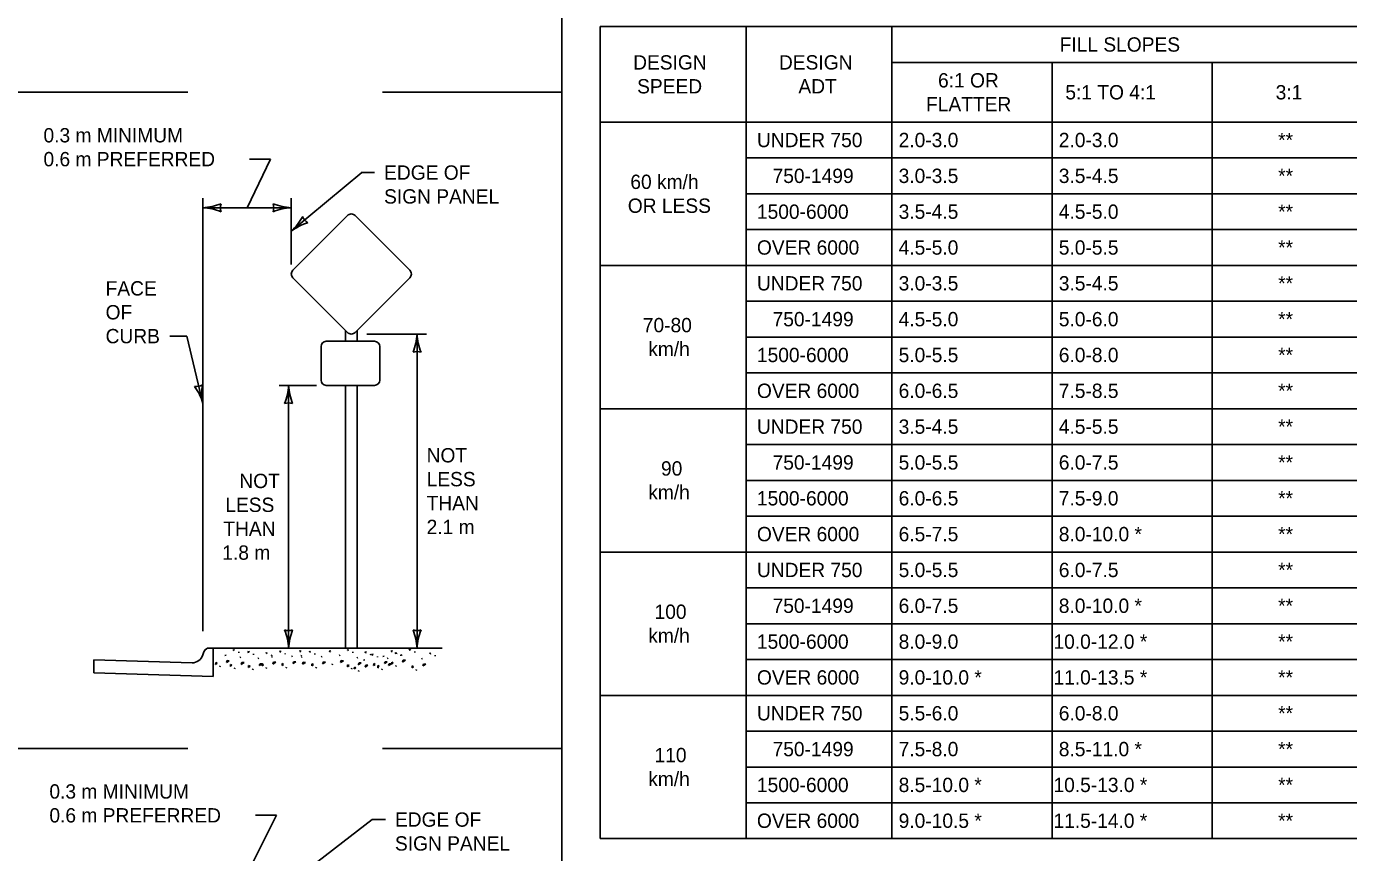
# Model space of a CAD drawing. Extents: x 49991.4 to 50021, y 49987.6 to 50011.4.
# Drawn here: x 50005.83 to 50011.36, y 49990.11 to 49993.57 of the extents above; entities that cross this region are included whole.
import ezdxf

# ---------------------------------------------------------------- set-up
doc = ezdxf.new("R2010")
doc.units = 0
for name, color, linetype in [('Level 1', 7, 'Continuous'), ('Level 2', 7, 'Continuous'), ('Level 3', 7, 'Continuous')]:
    doc.layers.add(name, color=color, linetype=linetype)

msp = doc.modelspace()

# ---------------------------------------------------------------- linework, layer by layer
at = {"layer": 'Level 1'}
for p, q in [((50006.9416, 49992.5484), (50007.1702, 49992.7772)), ((50007.202, 49992.7772), (50007.4309, 49992.5484)), ((50007.1702, 49992.2877), (50006.9416, 49992.5166)), ((50007.4309, 49992.5166), (50007.202, 49992.2877)), ((50007.1618, 49992.2506), (50007.1618, 49992.2961)), ((50007.2104, 49992.2506), (50007.2104, 49992.2961)), ((50007.0595, 49992.0878), (50007.0595, 49992.2291)), ((50007.081, 49992.2506), (50007.2836, 49992.2506)), ((50007.3051, 49992.2291), (50007.3051, 49992.0878)), ((50007.2836, 49992.0663), (50007.081, 49992.0663)), ((50007.1618, 49990.9661), (50007.1618, 49992.0663)), ((50007.2104, 49990.9661), (50007.2104, 49992.0663)), ((50006.6082, 49990.9661), (50006.5913, 49990.9661)), ((50006.6082, 49990.9661), (50007.5665, 49990.9661)), ((50006.6082, 49990.8476), (50006.6082, 49990.9661)), ((50006.6622, 49990.9368), (50006.6576, 49990.9352)), ((50006.6922, 49990.9563), (50006.6942, 49990.961)), ((50006.6966, 49990.9574), (50006.6922, 49990.9563)), ((50006.6942, 49990.961), (50006.6966, 49990.9574)), ((50006.7151, 49990.9467), (50006.7156, 49990.9503)), ((50006.7238, 49990.9288), (50006.7192, 49990.9272)), ((50006.7538, 49990.9483), (50006.7558, 49990.953)), ((50006.7583, 49990.9494), (50006.7538, 49990.9483)), ((50006.7558, 49990.953), (50006.7583, 49990.9494)), ((50006.7767, 49990.9387), (50006.7772, 49990.9423)), ((50006.7997, 49990.924), (50006.7951, 49990.9225)), ((50006.8297, 49990.9436), (50006.8318, 49990.9483)), ((50006.8342, 49990.9446), (50006.8297, 49990.9436)), ((50006.8318, 49990.9483), (50006.8342, 49990.9446)), ((50006.8566, 49990.9305), (50006.852, 49990.9289)), ((50006.8526, 49990.934), (50006.8531, 49990.9376)), ((50006.8866, 49990.95), (50006.8886, 49990.9547)), ((50006.8911, 49990.9511), (50006.8866, 49990.95)), ((50006.8886, 49990.9547), (50006.8911, 49990.9511)), ((50006.9095, 49990.9404), (50006.91, 49990.944)), ((50006.9404, 49990.932), (50006.9358, 49990.9305)), ((50006.9704, 49990.9516), (50006.9724, 49990.9563)), ((50006.9749, 49990.9527), (50006.9704, 49990.9516)), ((50006.9724, 49990.9563), (50006.9749, 49990.9527)), ((50006.9808, 49990.9298), (50006.9762, 49990.9282)), ((50006.9768, 49990.9333), (50006.9773, 49990.9369)), ((50007.0108, 49990.9493), (50007.0128, 49990.954)), ((50007.0153, 49990.9504), (50007.0108, 49990.9493)), ((50007.0128, 49990.954), (50007.0153, 49990.9504)), ((50007.0337, 49990.9397), (50007.0342, 49990.9433)), ((50007.0646, 49990.9313), (50007.06, 49990.9298)), ((50007.0946, 49990.9509), (50007.0966, 49990.9556)), ((50007.0991, 49990.952), (50007.0946, 49990.9509)), ((50007.0966, 49990.9556), (50007.0991, 49990.952)), ((50007.1396, 49990.9368), (50007.135, 49990.9352)), ((50007.1695, 49990.9563), (50007.1716, 49990.961)), ((50007.174, 49990.9574), (50007.1695, 49990.9563)), ((50007.1716, 49990.961), (50007.174, 49990.9574)), ((50007.1924, 49990.9467), (50007.1929, 49990.9503)), ((50007.2139, 49990.9272), (50007.2093, 49990.9256)), ((50007.2439, 49990.9467), (50007.2459, 49990.9514)), ((50007.2483, 49990.9478), (50007.2439, 49990.9467)), ((50007.2459, 49990.9514), (50007.2483, 49990.9478)), ((50007.2668, 49990.9371), (50007.2673, 49990.9408)), ((50007.2722, 49990.9372), (50007.2743, 49990.942)), ((50007.2767, 49990.9383), (50007.2722, 49990.9372)), ((50007.2743, 49990.942), (50007.2767, 49990.9383)), ((50007.2952, 49990.9277), (50007.2956, 49990.9313)), ((50007.3229, 49990.932), (50007.3183, 49990.9305)), ((50007.3403, 49990.924), (50007.3357, 49990.9225)), ((50007.3529, 49990.9516), (50007.355, 49990.9563)), ((50007.3574, 49990.9527), (50007.3529, 49990.9516)), ((50007.355, 49990.9563), (50007.3574, 49990.9527)), ((50007.3702, 49990.9436), (50007.3723, 49990.9483)), ((50007.3747, 49990.9446), (50007.3702, 49990.9436)), ((50007.3723, 49990.9483), (50007.3747, 49990.9446)), ((50007.3758, 49990.942), (50007.3763, 49990.9456)), ((50007.3932, 49990.934), (50007.3936, 49990.9376)), ((50007.3987, 49990.9383), (50007.3941, 49990.9368)), ((50007.4287, 49990.9579), (50007.4308, 49990.9626)), ((50007.4332, 49990.959), (50007.4287, 49990.9579)), ((50007.4308, 49990.9626), (50007.4332, 49990.959)), ((50007.4516, 49990.9483), (50007.4521, 49990.9519)), ((50007.5141, 49990.942), (50007.5161, 49990.9467)), ((50007.5186, 49990.9431), (50007.5141, 49990.942)), ((50007.5161, 49990.9467), (50007.5186, 49990.9431)), ((50007.537, 49990.9324), (50007.5375, 49990.936)), ((50006.5199, 49990.9044), (50006.1083, 49990.9168)), ((50006.1083, 49990.9168), (50006.1083, 49990.8627)), ((50006.6185, 49990.8978), (50006.619, 49990.9061)), ((50006.6248, 49990.9028), (50006.6185, 49990.8978)), ((50006.619, 49990.9061), (50006.6248, 49990.9028)), ((50006.6373, 49990.8916), (50006.6358, 49990.8874)), ((50006.6668, 49990.9137), (50006.6635, 49990.9058)), ((50006.6635, 49990.9058), (50006.6757, 49990.9135)), ((50006.6757, 49990.9135), (50006.6668, 49990.9137)), ((50006.6802, 49990.8898), (50006.6806, 49990.8981)), ((50006.6865, 49990.8948), (50006.6802, 49990.8898)), ((50006.6806, 49990.8981), (50006.6865, 49990.8948)), ((50006.6989, 49990.8836), (50006.6974, 49990.8794)), ((50006.7284, 49990.9057), (50006.7251, 49990.8978)), ((50006.7251, 49990.8978), (50006.7373, 49990.9055)), ((50006.7373, 49990.9055), (50006.7284, 49990.9057)), ((50006.7561, 49990.8851), (50006.7566, 49990.8933)), ((50006.7624, 49990.8901), (50006.7561, 49990.8851)), ((50006.7566, 49990.8933), (50006.7624, 49990.8901)), ((50006.7749, 49990.8789), (50006.7733, 49990.8747)), ((50006.8043, 49990.901), (50006.8011, 49990.8931)), ((50006.8011, 49990.8931), (50006.8132, 49990.9007)), ((50006.8132, 49990.9007), (50006.8043, 49990.901)), ((50006.813, 49990.8915), (50006.8134, 49990.8998)), ((50006.8193, 49990.8965), (50006.813, 49990.8915)), ((50006.8134, 49990.8998), (50006.8193, 49990.8965)), ((50006.8318, 49990.8853), (50006.8302, 49990.8811)), ((50006.8612, 49990.9074), (50006.8579, 49990.8995)), ((50006.8579, 49990.8995), (50006.8701, 49990.9072)), ((50006.8701, 49990.9072), (50006.8612, 49990.9074)), ((50006.8968, 49990.8931), (50006.8972, 49990.9013)), ((50006.9031, 49990.8981), (50006.8968, 49990.8931)), ((50006.8972, 49990.9013), (50006.9031, 49990.8981)), ((50006.9156, 49990.8869), (50006.914, 49990.8827)), ((50006.945, 49990.909), (50006.9418, 49990.9011)), ((50006.9418, 49990.9011), (50006.9539, 49990.9087)), ((50006.9539, 49990.9087), (50006.945, 49990.909)), ((50006.9854, 49990.9067), (50006.9821, 49990.8988)), ((50006.9821, 49990.8988), (50006.9943, 49990.9065)), ((50006.9943, 49990.9065), (50006.9854, 49990.9067)), ((50007.021, 49990.8924), (50007.0214, 49990.9006)), ((50007.0273, 49990.8974), (50007.021, 49990.8924)), ((50007.0214, 49990.9006), (50007.0273, 49990.8974)), ((50007.0398, 49990.8862), (50007.0382, 49990.882)), ((50007.0692, 49990.9083), (50007.066, 49990.9004)), ((50007.066, 49990.9004), (50007.0781, 49990.908)), ((50007.0781, 49990.908), (50007.0692, 49990.9083)), ((50007.1076, 49990.9008), (50007.106, 49990.8966)), ((50007.1442, 49990.9137), (50007.1409, 49990.9058)), ((50007.1409, 49990.9058), (50007.153, 49990.9135)), ((50007.153, 49990.9135), (50007.1442, 49990.9137)), ((50007.1702, 49990.8883), (50007.1707, 49990.8965)), ((50007.1766, 49990.8932), (50007.1702, 49990.8883)), ((50007.1707, 49990.8965), (50007.1766, 49990.8932)), ((50007.189, 49990.8821), (50007.1875, 49990.8778)), ((50007.1986, 49990.8788), (50007.1991, 49990.887)), ((50007.2049, 49990.8838), (50007.1986, 49990.8788)), ((50007.1991, 49990.887), (50007.2049, 49990.8838)), ((50007.2185, 49990.9041), (50007.2152, 49990.8963)), ((50007.2152, 49990.8963), (50007.2274, 49990.9039)), ((50007.2174, 49990.8726), (50007.2158, 49990.8684)), ((50007.2274, 49990.9039), (50007.2185, 49990.9041)), ((50007.2423, 49990.9177), (50007.2377, 49990.9161)), ((50007.2469, 49990.8947), (50007.2436, 49990.8868)), ((50007.2436, 49990.8868), (50007.2557, 49990.8944)), ((50007.2557, 49990.8944), (50007.2469, 49990.8947)), ((50007.2793, 49990.8931), (50007.2798, 49990.9013)), ((50007.2856, 49990.8981), (50007.2793, 49990.8931)), ((50007.2798, 49990.9013), (50007.2856, 49990.8981)), ((50007.2981, 49990.8869), (50007.2965, 49990.8827)), ((50007.2966, 49990.8851), (50007.2971, 49990.8933)), ((50007.3029, 49990.8901), (50007.2966, 49990.8851)), ((50007.2971, 49990.8933), (50007.3029, 49990.8901)), ((50007.3154, 49990.8789), (50007.3138, 49990.8747)), ((50007.3275, 49990.909), (50007.3243, 49990.9011)), ((50007.3243, 49990.9011), (50007.3364, 49990.9087)), ((50007.3364, 49990.9087), (50007.3275, 49990.909)), ((50007.3449, 49990.901), (50007.3416, 49990.8931)), ((50007.3416, 49990.8931), (50007.3537, 49990.9007)), ((50007.3537, 49990.9007), (50007.3449, 49990.901)), ((50007.3551, 49990.8994), (50007.3556, 49990.9077)), ((50007.3614, 49990.9044), (50007.3551, 49990.8994)), ((50007.3556, 49990.9077), (50007.3614, 49990.9044)), ((50007.3739, 49990.8932), (50007.3723, 49990.889)), ((50007.4033, 49990.9153), (50007.4001, 49990.9074)), ((50007.4001, 49990.9074), (50007.4122, 49990.9151)), ((50007.4122, 49990.9151), (50007.4033, 49990.9153)), ((50007.4405, 49990.8835), (50007.4409, 49990.8918)), ((50007.4468, 49990.8885), (50007.4405, 49990.8835)), ((50007.4409, 49990.8918), (50007.4468, 49990.8885)), ((50007.4593, 49990.8773), (50007.4577, 49990.8731)), ((50007.4841, 49990.9225), (50007.4795, 49990.9209)), ((50007.4887, 49990.8994), (50007.4855, 49990.8915)), ((50007.4855, 49990.8915), (50007.4976, 49990.8992)), ((50007.4976, 49990.8992), (50007.4887, 49990.8994)), ((50006.1083, 49990.8627), (50006.6082, 49990.8476))]:
    msp.add_line(p, q, dxfattribs=at)
for centre, radius, start, end in [((50007.1861, 49992.7613), 0.0225, 45.011, 135.022), ((50006.9575, 49992.5325), 0.0225, 135.022, 224.967), ((50007.415, 49992.5325), 0.0225, 315, 45.011), ((50007.1861, 49992.3036), 0.0225, 224.967, 315), ((50007.081, 49992.2291), 0.0215, 90, 180), ((50007.2836, 49992.2291), 0.0215, 0, 90), ((50007.081, 49992.0878), 0.0215, 180, 270), ((50007.2836, 49992.0878), 0.0215, 270, 0), ((50006.5195, 49990.9521), 0.0477, 270.4937, 342.4535), ((50006.616, 49990.9268), 0.0521, 147.9305, 167.8949), ((50006.5896, 49990.9468), 0.0194, 85.2356, 156.6889)]:
    msp.add_arc(centre, radius, start, end, dxfattribs=at)
at = {"layer": 'Level 2'}
for p, q in [((50008.2279, 49993.5684), (50013.4679, 49993.5684)), ((50008.2279, 49993.5684), (50008.2279, 49990.1684)), ((50008.8379, 49993.5684), (50008.8379, 49990.1684)), ((50009.4479, 49993.5684), (50009.4479, 49990.1684)), ((50009.4479, 49993.4184), (50013.4679, 49993.4184)), ((50010.1179, 49993.4184), (50010.1179, 49990.1684)), ((50010.7879, 49993.4184), (50010.7879, 49990.1684)), ((50008.2279, 49993.1684), (50013.4679, 49993.1684)), ((50008.8379, 49993.0184), (50013.4679, 49993.0184)), ((50008.8379, 49992.8684), (50013.4679, 49992.8684)), ((50008.8379, 49992.7184), (50013.4679, 49992.7184)), ((50008.2279, 49992.5684), (50013.4679, 49992.5684)), ((50008.8379, 49992.4184), (50013.4679, 49992.4184)), ((50008.8379, 49992.2684), (50013.4679, 49992.2684)), ((50008.8379, 49992.1184), (50013.4679, 49992.1184)), ((50008.2279, 49991.9684), (50013.4679, 49991.9684)), ((50008.8379, 49991.8184), (50013.4679, 49991.8184)), ((50008.8379, 49991.6684), (50013.4679, 49991.6684)), ((50008.8379, 49991.5184), (50013.4679, 49991.5184)), ((50008.2279, 49991.3684), (50013.4679, 49991.3684)), ((50008.8379, 49991.2184), (50013.4679, 49991.2184)), ((50008.8379, 49991.0684), (50013.4679, 49991.0684)), ((50008.8379, 49990.9184), (50013.4679, 49990.9184)), ((50008.2279, 49990.7684), (50013.4679, 49990.7684)), ((50008.8379, 49990.6184), (50013.4679, 49990.6184)), ((50008.8379, 49990.4684), (50013.4679, 49990.4684)), ((50008.8379, 49990.3184), (50013.4679, 49990.3184)), ((50008.2279, 49990.1684), (50013.4679, 49990.1684))]:
    msp.add_line(p, q, dxfattribs=at)
at = {"layer": 'Level 3'}
for p, q in [((50008.0668, 49994.0732), (50008.0668, 49987.7988)), ((50005.0025, 49993.2934), (50006.5025, 49993.2934)), ((50007.3168, 49993.2934), (50008.0668, 49993.2934)), ((50006.75, 49992.8101), (50006.8479, 49993.0134)), ((50006.8479, 49993.0134), (50006.7604, 49993.0134)), ((50006.935, 49992.7113), (50007.2298, 49992.9573)), ((50007.2278, 49992.9573), (50007.2832, 49992.9573)), ((50006.5651, 49991.0377), (50006.5651, 49992.8501)), ((50006.5651, 49992.8101), (50006.935, 49992.8101)), ((50006.935, 49992.5725), (50006.935, 49992.8501)), ((50006.4263, 49992.2724), (50006.4983, 49992.2724)), ((50006.4983, 49992.2724), (50006.5651, 49991.9909)), ((50007.2504, 49992.2811), (50007.5012, 49992.2811)), ((50007.4612, 49990.9661), (50007.4612, 49992.2811)), ((50006.8838, 49992.0663), (50007.041, 49992.0663)), ((50006.9238, 49990.9661), (50006.9238, 49992.0663)), ((50005.0025, 49990.5461), (50006.5025, 49990.5461)), ((50008.0668, 49990.5461), (50007.3168, 49990.5461)), ((50006.7714, 49990.0628), (50006.8726, 49990.2661)), ((50006.8726, 49990.2661), (50006.7851, 49990.2661)), ((50006.9534, 49990.0018), (50007.2733, 49990.2484)), ((50007.2733, 49990.2484), (50007.3287, 49990.2484))]:
    msp.add_line(p, q, dxfattribs=at)
for centre, radius, start, end in [((50006.5536, 49993.0428), 0.233, 272.8273, 292.0772), ((50006.5559, 49992.588), 0.2223, 67.456, 87.6395), ((50006.6933, 49992.8101), 0.0548, 162.1388, 197.8612), ((50006.9442, 49993.0322), 0.2223, 247.456, 267.6395), ((50006.8068, 49992.8101), 0.0548, 342.1388, 17.8612), ((50006.9465, 49992.5774), 0.233, 92.8273, 112.0772), ((50006.7771, 49992.8826), 0.233, 312.6731, 331.9229), ((50007.0334, 49992.7935), 0.0548, 201.9846, 237.707), ((50007.0703, 49992.5349), 0.2223, 107.3018, 127.4853), ((50007.2391, 49992.2903), 0.2223, 337.456, 357.6395), ((50007.6939, 49992.2926), 0.233, 182.8273, 202.0772), ((50007.4612, 49992.1529), 0.0548, 72.1388, 107.8612), ((50006.5347, 49992.1155), 0.0548, 265.8498, 301.5721), ((50006.3417, 49991.9246), 0.233, 16.5382, 35.7881), ((50006.783, 49992.0347), 0.2223, 171.1669, 191.3505), ((50006.7017, 49992.0755), 0.2223, 337.456, 357.6395), ((50007.1565, 49992.0778), 0.233, 182.8273, 202.0772), ((50006.9238, 49991.9381), 0.0548, 72.1388, 107.8612), ((50006.9238, 49991.0943), 0.0548, 252.1388, 287.8612), ((50006.6911, 49990.9546), 0.233, 2.8273, 22.0772), ((50007.1459, 49990.9569), 0.2223, 157.456, 177.6395), ((50007.4612, 49991.0943), 0.0548, 252.1388, 287.8612), ((50007.2285, 49990.9546), 0.233, 2.8273, 22.0772), ((50007.6833, 49990.9569), 0.2223, 157.456, 177.6395)]:
    msp.add_arc(centre, radius, start, end, dxfattribs=at)

# ---------------------------------------------------------------- texts
at = {"layer": 'Level 2'}
for s, p in [('FILL SLOPES', (50010.1495, 49993.4634)), ('DESIGN', (50008.3652, 49993.3885)), ('DESIGN', (50008.9752, 49993.3885)), ('6:1 OR', (50009.6408, 49993.3134)), ('SPEED', (50008.3818, 49993.2885)), ('ADT', (50009.0566, 49993.2885)), ('5:1 TO 4:1', (50010.1733, 49993.2634)), ('3:1', (50011.0533, 49993.2634)), ('FLATTER', (50009.5907, 49993.2134)), ('0.3 m MINIMUM', (50005.8983, 49993.0834)), ('UNDER 750', (50008.8831, 49993.0635)), (' 2.0-3.0', (50009.4537, 49993.0635)), (' 2.0-3.0', (50010.1237, 49993.0635)), ('**', (50011.0637, 49993.0634)), ('0.6 m PREFERRED', (50005.8983, 49992.9834)), ('EDGE OF', (50007.3232, 49992.9273)), ('750-1499', (50008.9486, 49992.9135)), (' 3.0-3.5', (50009.4537, 49992.9135)), (' 3.5-4.5', (50010.1237, 49992.9135)), ('**', (50011.0637, 49992.9134)), ('60 km/h', (50008.3535, 49992.8885)), ('SIGN PANEL', (50007.3232, 49992.8273)), ('OR LESS', (50008.3429, 49992.7885)), ('1500-6000', (50008.8831, 49992.7635)), (' 3.5-4.5', (50009.4537, 49992.7635)), (' 4.5-5.0', (50010.1237, 49992.7635)), ('**', (50011.0637, 49992.7634)), ('OVER 6000', (50008.8831, 49992.6135)), (' 4.5-5.0', (50009.4537, 49992.6135)), (' 5.0-5.5', (50010.1237, 49992.6135)), ('**', (50011.0637, 49992.6134)), ('FACE', (50006.1581, 49992.4424)), ('UNDER 750', (50008.8831, 49992.4635)), (' 3.0-3.5', (50009.4537, 49992.4635)), (' 3.5-4.5', (50010.1237, 49992.4635)), ('**', (50011.0637, 49992.4634)), ('OF', (50006.1581, 49992.3424)), ('750-1499', (50008.9486, 49992.3135)), (' 4.5-5.0', (50009.4537, 49992.3135)), (' 5.0-6.0', (50010.1237, 49992.3135)), ('**', (50011.0637, 49992.3134)), ('70-80', (50008.4057, 49992.2885)), ('CURB', (50006.1581, 49992.2424)), ('km/h', (50008.4284, 49992.1885)), ('1500-6000', (50008.8831, 49992.1635)), (' 5.0-5.5', (50009.4537, 49992.1635)), (' 6.0-8.0', (50010.1237, 49992.1635)), ('**', (50011.0637, 49992.1634)), ('OVER 6000', (50008.8831, 49992.0135)), (' 6.0-6.5', (50009.4537, 49992.0135)), (' 7.5-8.5', (50010.1237, 49992.0135)), ('**', (50011.0637, 49992.0134)), ('UNDER 750', (50008.8831, 49991.8635)), (' 3.5-4.5', (50009.4537, 49991.8635)), (' 4.5-5.5', (50010.1237, 49991.8635)), ('**', (50011.0637, 49991.8634)), ('NOT', (50007.5012, 49991.7436)), ('750-1499', (50008.9486, 49991.7135)), (' 5.0-5.5', (50009.4537, 49991.7135)), (' 6.0-7.5', (50010.1237, 49991.7135)), ('**', (50011.0637, 49991.7134)), ('LESS', (50007.5012, 49991.6436)), ('90', (50008.4818, 49991.6885)), ('NOT', (50006.7177, 49991.6362)), ('km/h', (50008.4284, 49991.5885)), ('LESS', (50006.6589, 49991.5362)), ('THAN', (50007.5012, 49991.5436)), ('1500-6000', (50008.8831, 49991.5635)), (' 6.0-6.5', (50009.4537, 49991.5635)), (' 7.5-9.0', (50010.1237, 49991.5635)), ('**', (50011.0637, 49991.5634)), ('THAN', (50006.6507, 49991.4362)), ('2.1 m', (50007.5012, 49991.4436)), ('OVER 6000', (50008.8831, 49991.4135)), (' 6.5-7.5', (50009.4537, 49991.4135)), (' 8.0-10.0 *', (50010.1237, 49991.4135)), ('**', (50011.0637, 49991.4134)), ('1.8 m', (50006.6464, 49991.3362)), ('UNDER 750', (50008.8831, 49991.2635)), (' 5.0-5.5', (50009.4537, 49991.2635)), (' 6.0-7.5', (50010.1237, 49991.2635)), ('**', (50011.0637, 49991.2634)), ('100', (50008.4548, 49991.0885)), ('750-1499', (50008.9486, 49991.1135)), (' 6.0-7.5', (50009.4537, 49991.1135)), (' 8.0-10.0 *', (50010.1237, 49991.1135)), ('**', (50011.0637, 49991.1134)), ('km/h', (50008.4284, 49990.9885)), ('1500-6000', (50008.8831, 49990.9635)), (' 8.0-9.0', (50009.4537, 49990.9635)), ('10.0-12.0 *', (50010.1237, 49990.9635)), ('**', (50011.0637, 49990.9634)), ('OVER 6000', (50008.8831, 49990.8135)), (' 9.0-10.0 *', (50009.4537, 49990.8135)), ('11.0-13.5 *', (50010.1237, 49990.8135)), ('**', (50011.0637, 49990.8134)), ('UNDER 750', (50008.8831, 49990.6635)), (' 5.5-6.0', (50009.4537, 49990.6635)), (' 6.0-8.0', (50010.1237, 49990.6635)), ('**', (50011.0637, 49990.6634)), ('110', (50008.4548, 49990.4885)), ('750-1499', (50008.9486, 49990.5135)), (' 7.5-8.0', (50009.4537, 49990.5135)), (' 8.5-11.0 *', (50010.1237, 49990.5135)), ('**', (50011.0637, 49990.5134)), ('km/h', (50008.4284, 49990.3885)), ('0.3 m MINIMUM', (50005.923, 49990.3361)), ('1500-6000', (50008.8831, 49990.3635)), (' 8.5-10.0 *', (50009.4537, 49990.3635)), ('10.5-13.0 *', (50010.1237, 49990.3635)), ('**', (50011.0637, 49990.3634)), ('0.6 m PREFERRED', (50005.923, 49990.2361)), ('EDGE OF', (50007.3687, 49990.2184)), ('OVER 6000', (50008.8831, 49990.2135)), (' 9.0-10.5 *', (50009.4537, 49990.2135)), ('11.5-14.0 *', (50010.1237, 49990.2135)), ('**', (50011.0637, 49990.2134)), ('SIGN PANEL', (50007.3687, 49990.1184))]:
    msp.add_text(s, height=0.06, dxfattribs=at).set_placement(p)

doc.saveas('drawing.dxf')
